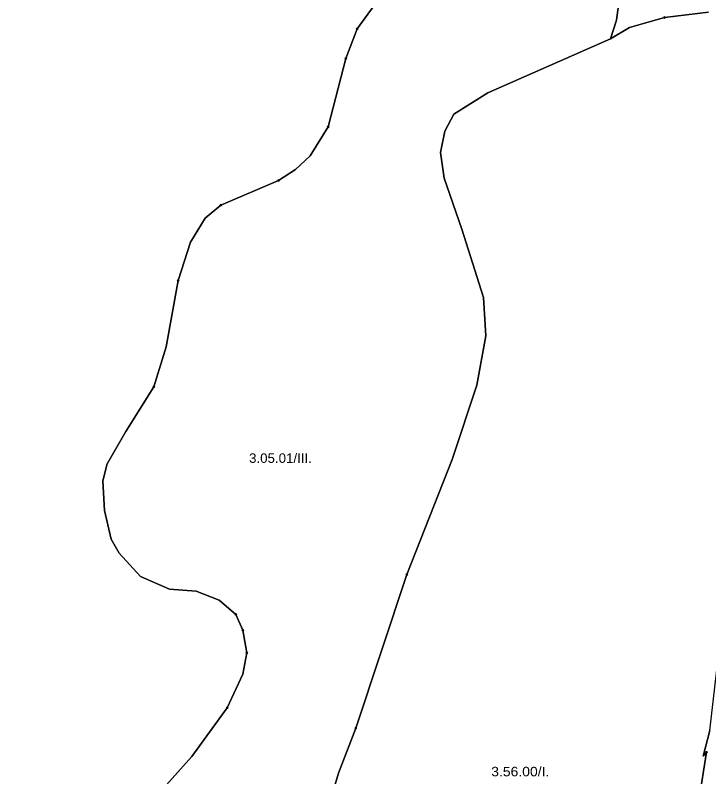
# Model space of a CAD drawing. Extents: x -650455 to -642254, y -1075222 to -1066610.
# Drawn here: x -646655 to -645923, y -1069709 to -1068906 of the extents above; entities that cross this region are included whole.
import ezdxf
from ezdxf.enums import TextEntityAlignment as Align

# ---------------------------------------------------------------- set-up
doc = ezdxf.new("R2010")
doc.units = 0
doc.header["$LTSCALE"] = 4
doc.header["$PDMODE"] = 32
doc.header["$PDSIZE"] = 2
for name, color, linetype, lineweight in [('1', 7, 'Continuous', 25), ('11', 7, 'Continuous', 13), ('13', 7, 'Continuous', 13), ('15', 7, 'Continuous', 13)]:
    doc.layers.add(name, color=color, linetype=linetype, lineweight=lineweight)
doc.layers.add('2', color=7, linetype='Continuous')

msp = doc.modelspace()

# ---------------------------------------------------------------- linework, layer by layer
at = {"layer": '1'}
for points in [[(-646377, -1069080), (-646359, -1069068.5), (-646343.5, -1069054.001), (-646324.5, -1069023.5), (-646306, -1068951.5), (-646294, -1068920.001), (-646277, -1068897.001), (-646250.5, -1068878), (-646240.5, -1068873.5), (-646174, -1068858.5), (-646125, -1068845), (-646115.5, -1068840.001), (-646096.5, -1068829.5), (-646075, -1068811.501), (-646038, -1068788.5), (-645980.5, -1068767.001), (-645968.5, -1068758.001), (-645975, -1068776.001), (-646007, -1068839.001), (-646013, -1068859.501), (-646020.25, -1068910.376), (-646020.269, -1068910.381), (-646020.5, -1068912.001), (-646026.5, -1068930.5)], [(-645923, -1068902.5), (-645969.5, -1068908.001), (-646006.5, -1068918.5), (-646026.5, -1068930.5), (-646020.5, -1068912.001), (-646020.269, -1068910.381), (-646020.25, -1068910.376), (-646013, -1068859.501)], [(-646385.5, -1069941.501), (-646359, -1069878.5), (-646346.5, -1069815.501), (-646313.5, -1069705.501), (-646295.5, -1069658.001), (-646241.5, -1069496.001), (-646193.5, -1069374.501), (-646167.5, -1069296), (-646158, -1069244.001), (-646160.5, -1069203.501), (-646183.5, -1069131.501), (-646202, -1069077.5), (-646206, -1069050.501), (-646201.5, -1069028), (-646192, -1069010.001), (-646156, -1068987.5), (-646026.5, -1068930.5), (-646006.5, -1068918.5), (-645969.5, -1068908.001), (-645923, -1068902.5)], [(-646277, -1068897.001), (-646294, -1068920.001), (-646306, -1068951.5), (-646324.5, -1069023.5), (-646343.5, -1069054.001), (-646359, -1069068.5), (-646377, -1069080)], [(-646026.5, -1068930.5), (-646156, -1068987.5), (-646192, -1069010.001), (-646201.5, -1069028), (-646206, -1069050.501), (-646202, -1069077.5), (-646183.5, -1069131.501), (-646160.5, -1069203.501), (-646158, -1069244.001), (-646167.5, -1069296), (-646193.5, -1069374.501), (-646241.5, -1069496.001), (-646295.5, -1069658.001), (-646313.5, -1069705.501), (-646346.5, -1069815.501)], [(-646563.5, -1069794), (-646468.5, -1069688), (-646431, -1069636.5), (-646414.5, -1069601.001), (-646410.5, -1069578.5), (-646414.5, -1069554.5), (-646422, -1069538), (-646439.5, -1069523), (-646464, -1069513.5), (-646492, -1069511.501), (-646522.5, -1069498), (-646545, -1069473.5), (-646553.5, -1069458.501), (-646560.5, -1069428.5), (-646562.5, -1069397), (-646558, -1069379.001), (-646538, -1069345), (-646508.5, -1069298.001), (-646495.5, -1069255.5), (-646483, -1069185.5), (-646470, -1069145), (-646454.5, -1069120.001), (-646438, -1069106), (-646377, -1069080)], [(-646377, -1069080), (-646438, -1069106), (-646454.5, -1069120.001), (-646470, -1069145), (-646483, -1069185.5), (-646495.5, -1069255.5), (-646508.5, -1069298.001), (-646538, -1069345), (-646558, -1069379.001), (-646562.5, -1069397), (-646560.5, -1069428.5), (-646553.5, -1069458.501), (-646545, -1069473.5), (-646522.5, -1069498), (-646492, -1069511.501), (-646464, -1069513.5), (-646439.5, -1069523), (-646422, -1069538), (-646414.5, -1069554.5), (-646410.5, -1069578.5), (-646414.5, -1069601.001), (-646431, -1069636.5), (-646468.5, -1069688), (-646563.5, -1069794)], [(-645960, -1069928), (-645957.5, -1069916.501), (-645945.5, -1069826), (-645941.5, -1069786), (-645925, -1069683.5), (-645928.5, -1069687.5), (-645921.5, -1069660.5), (-645908.5, -1069548.001), (-645886.5, -1069492.001), (-645856.5, -1069447.001), (-645698.133, -1069270.881), (-645694.109, -1069269.277), (-645694.125, -1069269.251), (-645637, -1069246.5), (-645633.75, -1069245.251), (-645633.394, -1069245.058), (-645602, -1069232.501), (-645598.374, -1069232.751)], [(-645921.5, -1069660.5), (-645928.5, -1069687.5), (-645925, -1069683.5), (-645941.5, -1069786)]]:
    msp.add_lwpolyline(points, dxfattribs=at)
at = {"layer": '11'}
for points in [[(-646377, -1069080), (-646359, -1069068.5), (-646343.5, -1069054.001), (-646324.5, -1069023.5), (-646306, -1068951.5), (-646294, -1068920.001), (-646277, -1068897.001), (-646250.5, -1068878), (-646240.5, -1068873.5), (-646174, -1068858.5), (-646125, -1068845), (-646115.5, -1068840.001), (-646096.5, -1068829.5), (-646109.312, -1068810.126), (-646116, -1068799.625)], [(-645923, -1068902.5), (-645969.5, -1068908.001), (-646006.5, -1068918.5), (-646026.5, -1068930.5), (-646156, -1068987.5), (-646192, -1069010.001), (-646201.5, -1069028), (-646206, -1069050.501), (-646202, -1069077.5), (-646183.5, -1069131.501), (-646160.5, -1069203.501), (-646158, -1069244.001)], [(-645941.5, -1069786), (-645925, -1069683.5), (-645928.5, -1069687.5), (-645921.5, -1069660.5), (-645908.5, -1069548.001), (-645886.5, -1069492.001), (-645856.5, -1069447.001), (-645698.133, -1069270.881), (-645695.195, -1069267.614), (-645695.188, -1069267.626), (-645687, -1069258.5), (-645636.5, -1069209.001), (-645431, -1069051.5), (-645370.25, -1069009.125)], [(-646431, -1069636.5), (-646414.5, -1069601.001), (-646410.5, -1069578.5), (-646414.5, -1069554.5), (-646422, -1069538), (-646439.5, -1069523), (-646464, -1069513.5), (-646492, -1069511.501), (-646522.5, -1069498), (-646545, -1069473.5), (-646553.5, -1069458.501), (-646560.5, -1069428.5), (-646562.5, -1069397), (-646558, -1069379.001), (-646538, -1069345), (-646508.5, -1069298.001), (-646495.5, -1069255.5), (-646483, -1069185.5), (-646470, -1069145), (-646454.5, -1069120.001), (-646438, -1069106), (-646377, -1069080)], [(-646158, -1069244.001), (-646167.5, -1069296), (-646193.5, -1069374.501), (-646241.5, -1069496.001), (-646295.5, -1069658.001), (-646313.5, -1069705.501), (-646346.5, -1069815.501), (-646359, -1069878.5)], [(-646606.5, -1069833.5), (-646563.5, -1069794), (-646468.5, -1069688), (-646431, -1069636.5)]]:
    msp.add_lwpolyline(points, dxfattribs=at)
for p in [(-646377, -1069080), (-646431, -1069636.5)]:
    msp.add_point(p, dxfattribs=at)
at = {"layer": '13'}
for p, q in [((-646294, -1068920.001), (-646306, -1068951.5)), ((-646306, -1068951.5), (-646324.5, -1069023.5)), ((-646295.5, -1069658.001), (-646241.5, -1069496.001)), ((-646422, -1069538), (-646414.5, -1069554.5)), ((-646414.5, -1069554.5), (-646410.5, -1069578.5))]:
    msp.add_line(p, q, dxfattribs=at)
for points in [[(-646241.5, -1069496.001), (-646193.5, -1069374.501), (-646167.5, -1069296), (-646158, -1069244.001), (-646160.5, -1069203.501), (-646183.5, -1069131.501), (-646202, -1069077.5), (-646206, -1069050.501), (-646201.5, -1069028), (-646192, -1069010.001), (-646156, -1068987.5), (-646026.5, -1068930.5), (-646020.5, -1068912.001), (-646020.269, -1068910.381), (-646020.25, -1068910.376), (-646013, -1068859.501), (-646007, -1068839.001), (-645975, -1068776.001), (-645968.5, -1068758.001), (-645980.5, -1068767.001), (-646038, -1068788.5)], [(-646038, -1068788.5), (-646075, -1068811.501), (-646096.5, -1068829.5), (-646115.5, -1068840.001), (-646125, -1068845), (-646174, -1068858.5), (-646240.5, -1068873.5), (-646250.5, -1068878), (-646277, -1068897.001), (-646294, -1068920.001)], [(-646013, -1068859.501), (-646020.25, -1068910.376), (-646020.269, -1068910.381), (-646020.5, -1068912.001), (-646026.5, -1068930.5), (-646006.5, -1068918.5), (-645969.5, -1068908.001), (-645923, -1068902.5)], [(-646324.5, -1069023.5), (-646343.5, -1069054.001), (-646359, -1069068.5), (-646377, -1069080), (-646438, -1069106)], [(-646438, -1069106), (-646454.5, -1069120.001), (-646470, -1069145), (-646483, -1069185.5)], [(-646483, -1069185.5), (-646495.5, -1069255.5), (-646508.5, -1069298.001)], [(-646508.5, -1069298.001), (-646538, -1069345), (-646558, -1069379.001), (-646562.5, -1069397), (-646560.5, -1069428.5), (-646553.5, -1069458.501), (-646545, -1069473.5), (-646522.5, -1069498), (-646492, -1069511.501), (-646464, -1069513.5), (-646439.5, -1069523), (-646422, -1069538)], [(-646410.5, -1069578.5), (-646414.5, -1069601.001), (-646431, -1069636.5), (-646468.5, -1069688), (-646563.5, -1069794), (-646606.5, -1069833.5), (-646615.709, -1069847.074), (-646654.889, -1069873.389)], [(-646346.5, -1069815.501), (-646313.5, -1069705.501), (-646295.5, -1069658.001)]]:
    msp.add_lwpolyline(points, dxfattribs=at)
for p in [(-645969.5, -1068908.001), (-646294, -1068920.001), (-646306, -1068951.5), (-646324.5, -1069023.5), (-646438, -1069106), (-646483, -1069185.5), (-646508.5, -1069298.001), (-646241.5, -1069496.001), (-646422, -1069538), (-646414.5, -1069554.5), (-646410.5, -1069578.5), (-646295.5, -1069658.001)]:
    msp.add_point(p, dxfattribs=at)
at = {"layer": '15'}
for points in [[(-645921.5, -1069660.5), (-645928.5, -1069687.5), (-645925, -1069683.5)], [(-645925, -1069683.5), (-645941.5, -1069786), (-645945.5, -1069826)]]:
    msp.add_lwpolyline(points, dxfattribs=at)
msp.add_point((-645925, -1069683.5), dxfattribs=at)

# ---------------------------------------------------------------- texts
at = {"layer": '2'}
for s, width, p in [('3.05.01/III.', 1.05, (-646374.865, -1069378.068)), ('3.56.00/I.', 1.1, (-646121.73, -1069708.845))]:
    msp.add_text(s, height=10, dxfattribs=dict(at, width=width)).set_placement(p, align=Align.CENTER)

doc.saveas('drawing.dxf')
